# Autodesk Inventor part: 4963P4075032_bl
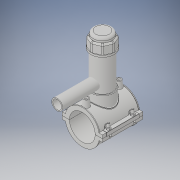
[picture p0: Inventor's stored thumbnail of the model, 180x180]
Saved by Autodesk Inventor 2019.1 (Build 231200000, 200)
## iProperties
Created: 2017-07
Part Number: 4963P4075032_bl
Material: Generic
Document SubType Name: Modeling
Designer: KIM
Density: 1 g/cm^3
Appearance: Default
Author: KIM
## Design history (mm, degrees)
derived "4963P4.ipt"
feature "Solid1::4963P4.ipt" dims "ScaleForDerivedMember" = 10
feature "Solid2::4963P4.ipt" dims "ScaleForDerivedMember" = 10
feature "Solid3::4963P4.ipt" dims "ScaleForDerivedMember" = 10
tag "TaggingFeature1"
body "Solid1"
body "Solid2"
body "Solid3"
other parameters: "d_" = 75 [user parameter], "B_" = 117 [user parameter], "L_" = 118 [user parameter], "d_t" = 6 [user parameter], "H_2" = 177 [user parameter], "H_1" = 56 [user parameter], "d_1" = 32 [user parameter], "H_" = 132 [user parameter], "d1" = 97.5 [user parameter], "d148" = 1.125 [user parameter], "d160" = 1.125 [user parameter], "d169" = 3.75 [user parameter], "d192" = 8 [user parameter], "d0" = 75 [user parameter], "d2" = 117 [user parameter], "d3" = 18.75 [user parameter], "d4" = 118 [user parameter], "d5" = 0 [user parameter], "d6" = 0.1 [user parameter], "d8" = 0 [user parameter], "d19" = 6 [user parameter], "d20" = 6 [user parameter], "d21" = 70.8 [user parameter], "d23" = 0 [user parameter], "d24" = 35.4 [user parameter], "d26" = 0 [user parameter], "d27" = 3 [user parameter], "d28" = 3 [user parameter], "d29" = 3 [user parameter], "d30" = 25 [user parameter], "d31" = 6 [user parameter], "d32" = 0 [user parameter], "d33" = 0 [user parameter], "d34" = 0.6 [user parameter], "d40" = 50.7 [user parameter], "d41" = 67.5 [user parameter], "d43" = 0 [user parameter], "d45" = 0 [user parameter], "d47" = 119.55 [user parameter], "d70" = 15 [user parameter], "d72" = 0 [user parameter], "d73" = 6 [user parameter], "d75" = 5 [user parameter], "d76" = 0 [user parameter], "d77" = 3.75 [user parameter], "d78" = 67.5 [user parameter], "d79" = 15 [user parameter], "d80" = 47.2 [user parameter], "d82" = 5 deg [user parameter], "d84" = 4 [user parameter], "d85" = 14 [user parameter], "d86" = 0 [user parameter], "d87" = 3 [user parameter], "d88" = 0 [user parameter], "d89" = 1 [user parameter], "d90" = 1 [user parameter], "d91" = 94.4 [user parameter], "d92" = 0 [user parameter], "d93" = 0.5 [user parameter], "d94" = 39.47368 [user parameter], "d96" = 99.45 [user parameter], "d97" = 2.36 [user parameter], "d98" = 0 [user parameter], "d102" = 0.75 [user parameter], "d120" = 140 deg [user parameter], "d121" = 24.228 [user parameter], "d122" = 20 deg [user parameter], "d123" = 195 [user parameter], "d124" = 58.5 [user parameter], "d126" = 0 [user parameter], "d143" = 77.25 [user parameter], "d145" = 17.30769 [user parameter], "d149" = 1.125 [user parameter], "d150" = 19.03846 [user parameter], "d153" = 118 [user parameter], "d154" = 0 [user parameter], "d156" = 48.75 [user parameter], "d157" = 160 deg [user parameter], "d159" = 4.5 [user parameter], "d161" = 1.125 [user parameter], "d162" = 70.8 [user parameter], "d163" = 0 [user parameter], "d164" = 37.5 [user parameter], "d167" = 7.5 [user parameter], "d168" = 47.56098 [user parameter], "d170" = 3.75 [user parameter], "d172" = 0 [user parameter], "d173" = 1 [user parameter], "d175" = 37.5 [user parameter], "d176" = 20 deg [user parameter], "d177" = 5.25 [user parameter], "d178" = 22.5 [user parameter], "d180" = 0 [user parameter], "d183" = 9 [user parameter], "d184" = 4.2 [user parameter], "d185" = 38.35 [user parameter], "d186" = 38.35 [user parameter], "d187" = 48.75 [user parameter], "d188" = 6.75 [user parameter], "d189" = 5.25 [user parameter], "d190" = 0 [user parameter], "d191" = 73.125 [user parameter], "d193" = 8 [user parameter], "d194" = 4.13 [user parameter], "d195" = 90 deg [user parameter], "d197" = 0 [user parameter], "d199" = 0 [user parameter], "d200" = 11.25 [user parameter], "d202" = 0 [user parameter], "d203" = 177 [user parameter], "d204" = 64.125 [user parameter], "d205" = 47.25 [user parameter], "d206" = 57.375 [user parameter], "d207" = 132.75 [user parameter], "d208" = 138.06 [user parameter], "d209" = 164.61 [user parameter], "d210" = 58.05 [user parameter], "d211" = 67.5 [user parameter], "d212" = 54 [user parameter], "d213" = 36 [user parameter]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
